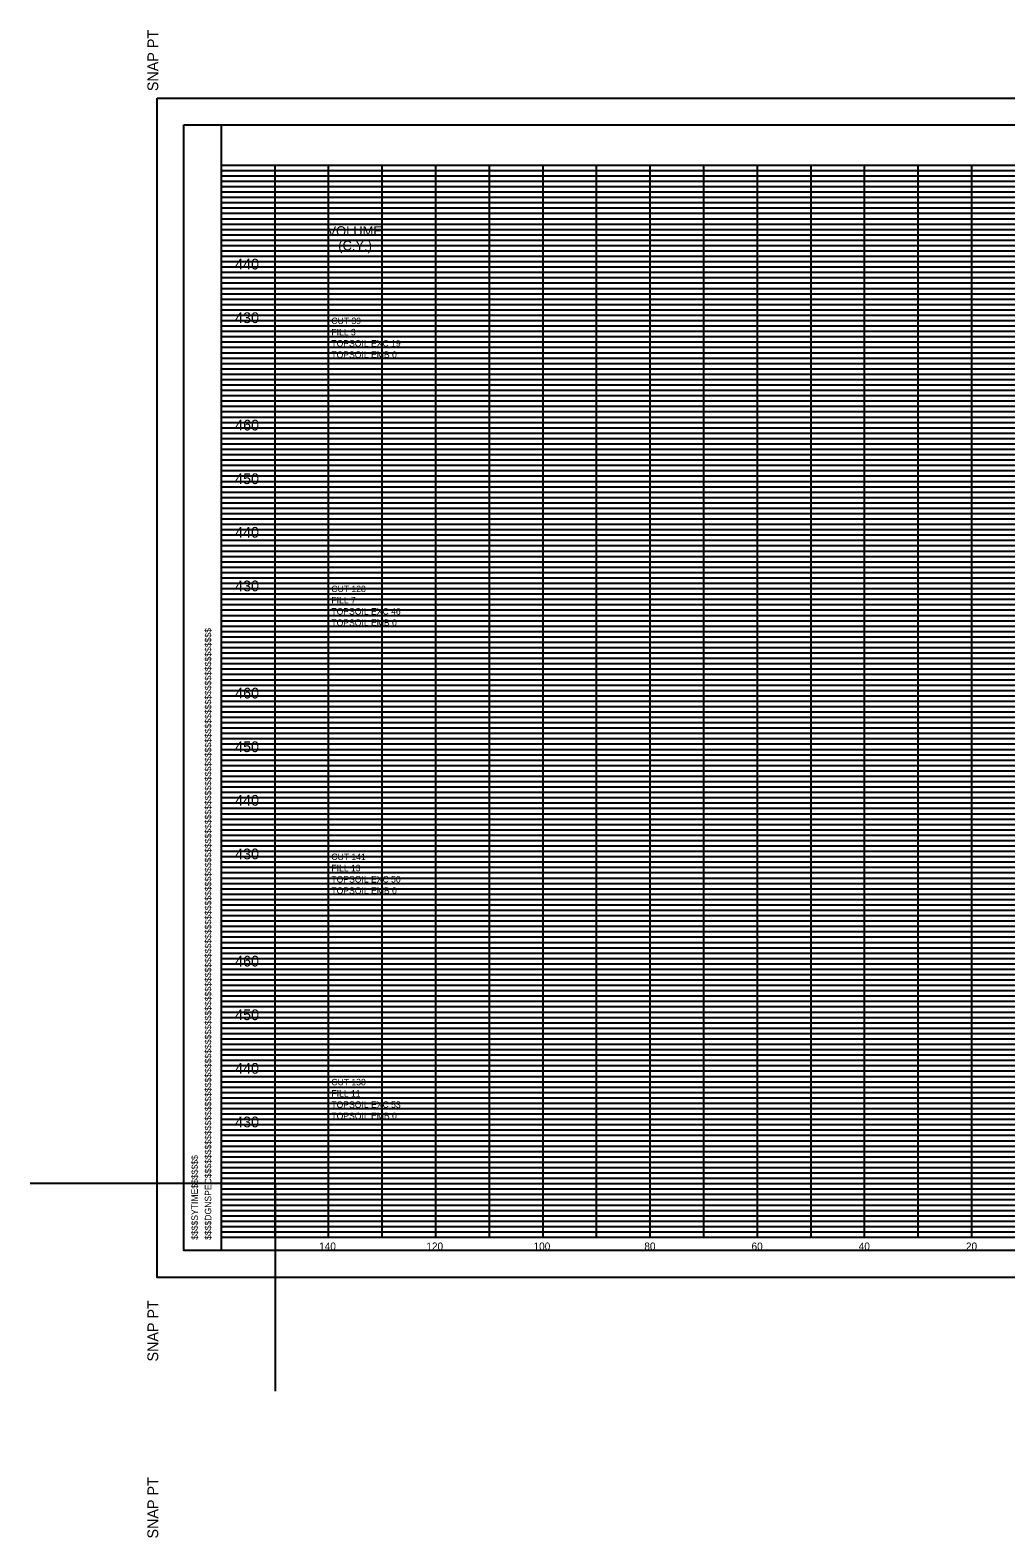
# Model space of a CAD drawing. Extents: x 37 to 1710, y 707 to 2305.
# Drawn here: x 1344.3 to 1526.3, y 1213.9 to 1495.2 of the extents above; entities that cross this region are included whole.
import ezdxf

# ---------------------------------------------------------------- set-up
doc = ezdxf.new("R2010")
doc.units = 0
for name, color, linetype in [('DESIGN - SCRATCH - User 1', 7, 'Continuous'), ('DESIGN - SHEET - Corner Text', 7, 'Continuous'), ('DESIGN - SHEET - Light Grid', 7, 'Continuous'), ('DESIGN - SHEET - Linework', 7, 'Continuous'), ('DESIGN - SHEET - Plot Shape', 7, 'Continuous'), ('DESIGN - TYPICAL - Text', 7, 'Continuous')]:
    doc.layers.add(name, color=color, linetype=linetype)

msp = doc.modelspace()

# ---------------------------------------------------------------- linework, layer by layer
at = {"layer": 'DESIGN - SCRATCH - User 1'}
for p, q in [((1390, 1280), (1344.31, 1280)), ((1390, 1280), (1390, 1241.3)), ((1380, 1270), (1380, 1270))]:
    msp.add_line(p, q, dxfattribs=at)
at = {"layer": 'DESIGN - SHEET - Light Grid'}
for p, q in [((1380, 1469), (1660, 1469)), ((1380, 1468), (1660, 1468)), ((1380, 1467), (1660, 1467)), ((1380, 1466), (1660, 1466)), ((1380, 1465), (1660, 1465)), ((1380, 1464), (1660, 1464)), ((1380, 1463), (1660, 1463)), ((1380, 1462), (1660, 1462)), ((1380, 1461), (1660, 1461)), ((1380, 1459), (1700, 1459)), ((1380, 1458), (1700, 1458)), ((1380, 1457), (1700, 1457)), ((1380, 1456), (1700, 1456)), ((1380, 1455), (1700, 1455)), ((1380, 1454), (1700, 1454)), ((1380, 1453), (1700, 1453)), ((1380, 1452), (1700, 1452)), ((1380, 1451), (1700, 1451)), ((1380, 1449), (1700, 1449)), ((1380, 1448), (1700, 1448)), ((1380, 1447), (1700, 1447)), ((1380, 1446), (1700, 1446)), ((1380, 1445), (1700, 1445)), ((1380, 1444), (1700, 1444)), ((1380, 1443), (1700, 1443)), ((1380, 1442), (1700, 1442)), ((1380, 1441), (1700, 1441)), ((1380, 1439), (1700, 1439)), ((1380, 1438), (1700, 1438)), ((1380, 1437), (1700, 1437)), ((1380, 1436), (1700, 1436)), ((1380, 1435), (1700, 1435)), ((1380, 1434), (1700, 1434)), ((1380, 1433), (1700, 1433)), ((1380, 1432), (1700, 1432)), ((1380, 1431), (1700, 1431)), ((1380, 1429), (1700, 1429)), ((1380, 1428), (1700, 1428)), ((1380, 1427), (1700, 1427)), ((1380, 1426), (1700, 1426)), ((1380, 1425), (1700, 1425)), ((1380, 1424), (1700, 1424)), ((1380, 1423), (1700, 1423)), ((1380, 1422), (1700, 1422)), ((1380, 1421), (1700, 1421)), ((1380, 1419), (1700, 1419)), ((1380, 1418), (1700, 1418)), ((1380, 1417), (1700, 1417)), ((1380, 1416), (1700, 1416)), ((1380, 1415), (1700, 1415)), ((1380, 1414), (1700, 1414)), ((1380, 1413), (1700, 1413)), ((1380, 1412), (1700, 1412)), ((1380, 1411), (1700, 1411)), ((1380, 1409), (1700, 1409)), ((1380, 1408), (1700, 1408)), ((1380, 1407), (1700, 1407)), ((1380, 1406), (1700, 1406)), ((1380, 1405), (1700, 1405)), ((1380, 1404), (1700, 1404)), ((1380, 1403), (1700, 1403)), ((1380, 1402), (1700, 1402)), ((1380, 1401), (1700, 1401)), ((1380, 1399), (1700, 1399)), ((1380, 1398), (1700, 1398)), ((1380, 1397), (1700, 1397)), ((1380, 1396), (1700, 1396)), ((1380, 1395), (1700, 1395)), ((1380, 1394), (1700, 1394)), ((1380, 1393), (1700, 1393)), ((1380, 1392), (1700, 1392)), ((1380, 1391), (1700, 1391)), ((1380, 1389), (1700, 1389)), ((1380, 1388), (1700, 1388)), ((1380, 1387), (1700, 1387)), ((1380, 1386), (1700, 1386)), ((1380, 1385), (1700, 1385)), ((1380, 1384), (1700, 1384)), ((1380, 1383), (1700, 1383)), ((1380, 1382), (1700, 1382)), ((1380, 1381), (1700, 1381)), ((1380, 1379), (1700, 1379)), ((1380, 1378), (1700, 1378)), ((1380, 1377), (1700, 1377)), ((1380, 1376), (1700, 1376)), ((1380, 1375), (1700, 1375)), ((1380, 1374), (1700, 1374)), ((1380, 1373), (1700, 1373)), ((1380, 1372), (1700, 1372)), ((1380, 1371), (1700, 1371)), ((1380, 1369), (1700, 1369)), ((1380, 1368), (1700, 1368)), ((1380, 1367), (1700, 1367)), ((1380, 1366), (1700, 1366)), ((1380, 1365), (1700, 1365)), ((1380, 1364), (1700, 1364)), ((1380, 1363), (1700, 1363)), ((1380, 1362), (1700, 1362)), ((1380, 1361), (1700, 1361)), ((1380, 1359), (1700, 1359)), ((1380, 1358), (1700, 1358)), ((1380, 1357), (1700, 1357)), ((1380, 1356), (1700, 1356)), ((1380, 1355), (1700, 1355)), ((1380, 1354), (1700, 1354)), ((1380, 1353), (1700, 1353)), ((1380, 1352), (1700, 1352)), ((1380, 1351), (1700, 1351)), ((1380, 1349), (1700, 1349)), ((1380, 1348), (1700, 1348)), ((1380, 1347), (1700, 1347)), ((1380, 1346), (1700, 1346)), ((1380, 1345), (1700, 1345)), ((1380, 1344), (1700, 1344)), ((1380, 1343), (1700, 1343)), ((1380, 1342), (1700, 1342)), ((1380, 1341), (1700, 1341)), ((1380, 1339), (1700, 1339)), ((1380, 1338), (1700, 1338)), ((1380, 1337), (1700, 1337)), ((1380, 1336), (1700, 1336)), ((1380, 1335), (1700, 1335)), ((1380, 1334), (1700, 1334)), ((1380, 1333), (1700, 1333)), ((1380, 1332), (1700, 1332)), ((1380, 1331), (1700, 1331)), ((1380, 1329), (1700, 1329)), ((1380, 1328), (1700, 1328)), ((1380, 1327), (1700, 1327)), ((1380, 1326), (1700, 1326)), ((1380, 1325), (1700, 1325)), ((1380, 1324), (1700, 1324)), ((1380, 1323), (1700, 1323)), ((1380, 1322), (1700, 1322)), ((1380, 1321), (1700, 1321)), ((1380, 1319), (1700, 1319)), ((1380, 1318), (1700, 1318)), ((1380, 1317), (1700, 1317)), ((1380, 1316), (1700, 1316)), ((1380, 1315), (1700, 1315)), ((1380, 1314), (1700, 1314)), ((1380, 1313), (1700, 1313)), ((1380, 1312), (1700, 1312)), ((1380, 1311), (1700, 1311)), ((1380, 1309), (1700, 1309)), ((1380, 1308), (1700, 1308)), ((1380, 1307), (1700, 1307)), ((1380, 1306), (1700, 1306)), ((1380, 1305), (1700, 1305)), ((1380, 1304), (1700, 1304)), ((1380, 1303), (1700, 1303)), ((1380, 1302), (1700, 1302)), ((1380, 1301), (1700, 1301)), ((1380, 1299), (1700, 1299)), ((1380, 1298), (1700, 1298)), ((1380, 1297), (1700, 1297)), ((1380, 1296), (1700, 1296)), ((1380, 1295), (1700, 1295)), ((1380, 1294), (1700, 1294)), ((1380, 1293), (1700, 1293)), ((1380, 1292), (1700, 1292)), ((1380, 1291), (1700, 1291)), ((1380, 1289), (1700, 1289)), ((1380, 1288), (1700, 1288)), ((1380, 1287), (1700, 1287)), ((1380, 1286), (1700, 1286)), ((1380, 1285), (1700, 1285)), ((1380, 1284), (1700, 1284)), ((1380, 1283), (1700, 1283)), ((1380, 1282), (1700, 1282)), ((1380, 1281), (1700, 1281)), ((1380, 1279), (1700, 1279)), ((1380, 1278), (1700, 1278)), ((1380, 1277), (1700, 1277)), ((1380, 1276), (1700, 1276)), ((1380, 1275), (1700, 1275)), ((1380, 1274), (1700, 1274)), ((1380, 1273), (1700, 1273)), ((1380, 1272), (1700, 1272)), ((1380, 1271), (1700, 1271))]:
    msp.add_line(p, q, dxfattribs=at)
at = {"layer": 'DESIGN - SHEET - Linework'}
for p, q in [((1380, 1470), (1700, 1470)), ((1390, 1270), (1390, 1470)), ((1400, 1270), (1400, 1470)), ((1410, 1270), (1410, 1470)), ((1420, 1270), (1420, 1470)), ((1430, 1270), (1430, 1470)), ((1440, 1270), (1440, 1470)), ((1450, 1270), (1450, 1470)), ((1460, 1270), (1460, 1470)), ((1470, 1270), (1470, 1470)), ((1480, 1270), (1480, 1470)), ((1490, 1270), (1490, 1470)), ((1500, 1270), (1500, 1470)), ((1510, 1270), (1510, 1470)), ((1520, 1270), (1520, 1470)), ((1380, 1460), (1700, 1460)), ((1380, 1450), (1700, 1450)), ((1380, 1440), (1700, 1440)), ((1380, 1430), (1700, 1430)), ((1380, 1420), (1700, 1420)), ((1380, 1410), (1700, 1410)), ((1380, 1400), (1700, 1400)), ((1380, 1390), (1700, 1390)), ((1380, 1380), (1700, 1380)), ((1380, 1370), (1700, 1370)), ((1380, 1360), (1700, 1360)), ((1380, 1350), (1700, 1350)), ((1380, 1340), (1700, 1340)), ((1380, 1330), (1700, 1330)), ((1380, 1320), (1700, 1320)), ((1380, 1310), (1700, 1310)), ((1380, 1300), (1700, 1300)), ((1380, 1290), (1700, 1290)), ((1380, 1280), (1700, 1280)), ((1380, 1270), (1700, 1270))]:
    msp.add_line(p, q, dxfattribs=at)
for points in [[(1368, 1482.5), (1708, 1482.5), (1708, 1262.5), (1368, 1262.5)], [(1380, 1477.5), (1700, 1477.5), (1700, 1267.5), (1380, 1267.5)]]:
    msp.add_lwpolyline(points, close=True, dxfattribs=at)
at = {"layer": 'DESIGN - SHEET - Plot Shape'}
msp.add_lwpolyline([(1373, 1477.5), (1703, 1477.5), (1703, 1267.5), (1373, 1267.5)], close=True, dxfattribs=at)

# ---------------------------------------------------------------- texts
at = {"layer": 'DESIGN - SHEET - Corner Text'}
for s, height, p in [('  SNAP PT', 2, (1368.2, 1482.3)), ('$$$$DGNSPEC$$$$$$$$$$$$$$$$$$$$$$$$$$$$$$$$$$$$$$$$$$$$$$$$$$$$$$$$$$$$$$$$$$$$$$$$$$$$$$$$$$$$$$$$$$$$$$$$$$$$$$$$$$$$$$$$$$$', 1.2, (1378.1, 1269.5)), ('$$$$SYTIME$$$$$$$', 1.2, (1375.6, 1269.5)), ('SNAP PT  ', 2, (1368.2, 1246.8)), ('  SNAP PT', 2, (1368.2, 1212.3))]:
    msp.add_text(s, height=height, rotation=90, dxfattribs=at).set_placement(p)
at = {"layer": 'DESIGN - TYPICAL - Text'}
for s, height, p in [('VOLUME', 1.8, (1399.79, 1456.79)), ('   (C.Y.)', 1.8, (1399.79, 1454.09)), ('     440     ', 2, (1378.84, 1450.53)), ('     430     ', 2, (1378.84, 1440.53)), ('CUT 39', 1.2, (1400.51, 1440.34)), ('TOPSOIL EXC 19', 1.2, (1400.51, 1436.14)), ('FILL 3', 1.2, (1400.51, 1438.24)), ('TOPSOIL EMB 0', 1.2, (1400.51, 1434.04)), ('     460     ', 2, (1378.84, 1420.49)), ('     450     ', 2, (1378.84, 1410.49)), ('     440     ', 2, (1378.84, 1400.49)), ('     430     ', 2, (1378.84, 1390.49)), ('CUT 128', 1.2, (1400.51, 1390.34)), ('FILL 7', 1.2, (1400.51, 1388.24)), ('TOPSOIL EXC 46', 1.2, (1400.51, 1386.14)), ('TOPSOIL EMB 0', 1.2, (1400.51, 1384.04)), ('     460     ', 2, (1378.84, 1370.49)), ('     450     ', 2, (1378.84, 1360.49)), ('     440     ', 2, (1378.84, 1350.49)), ('     430     ', 2, (1378.84, 1340.49)), ('CUT 141', 1.2, (1400.51, 1340.36)), ('FILL 13', 1.2, (1400.51, 1338.26)), ('TOPSOIL EXC 50', 1.2, (1400.51, 1336.16)), ('TOPSOIL EMB 0', 1.2, (1400.51, 1334.06)), ('     460     ', 2, (1378.84, 1320.49)), ('     450     ', 2, (1378.84, 1310.49)), ('     440     ', 2, (1378.84, 1300.49)), ('CUT 138', 1.2, (1400.51, 1298.33)), ('FILL 11', 1.2, (1400.51, 1296.23)), ('TOPSOIL EXC 53', 1.2, (1400.51, 1294.13)), ('     430     ', 2, (1378.84, 1290.49)), ('TOPSOIL EMB 0', 1.2, (1400.51, 1292.03)), ('     140     ', 1.4, (1395.63, 1267.6)), ('     120     ', 1.4, (1415.63, 1267.6)), ('     100     ', 1.4, (1435.63, 1267.6)), ('     80     ', 1.4, (1456.3, 1267.6)), ('     60     ', 1.4, (1476.3, 1267.6)), ('     40     ', 1.4, (1496.3, 1267.6)), ('     20     ', 1.4, (1516.3, 1267.6))]:
    msp.add_text(s, height=height, dxfattribs=at).set_placement(p)

doc.saveas('drawing.dxf')
